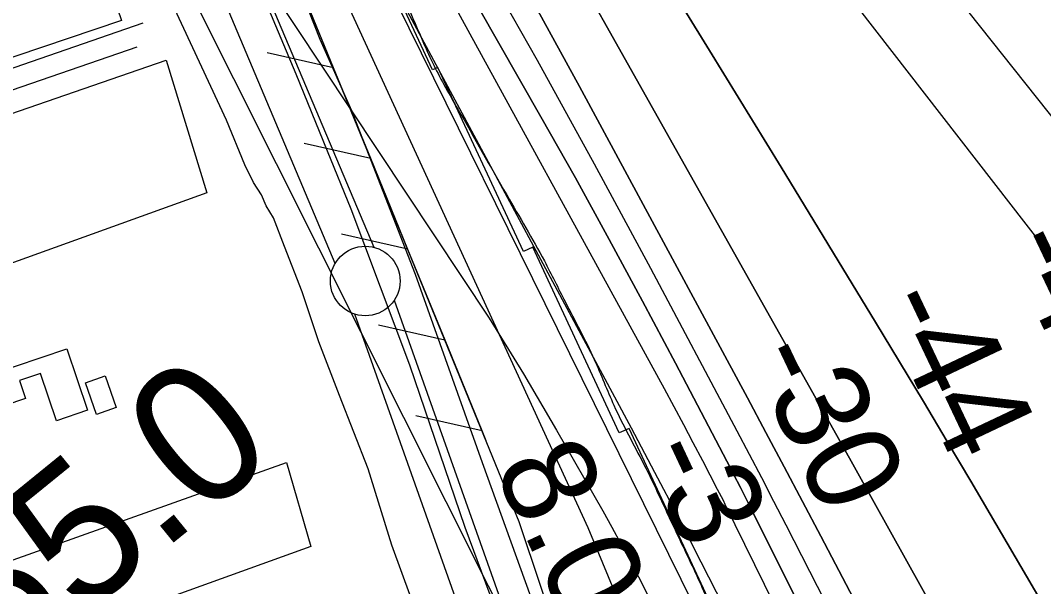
# Model space of a CAD drawing. Extents: x 3684037 to 3722149, y 433263 to 459021.
# Drawn here: x 3705202 to 3705935, y 447573 to 447979 of the extents above; entities that cross this region are included whole.
import ezdxf

# ---------------------------------------------------------------- set-up
doc = ezdxf.new("R2010")
doc.units = 0
for name, color, linetype in [('V-BLDG-OTLN', 7, 'Continuous'), ('V-DTCH-CNTR', 7, 'Continuous'), ('V-FLOD-BASE', 7, 'Continuous'), ('V-LEVE-TOET', 7, 'Continuous'), ('V-RIVR-EDGE', 7, 'Continuous'), ('V-RIVR-RANG', 7, 'Continuous'), ('V-RRAP-FSHR', 7, 'Continuous'), ('V-RRAP-RVMT', 7, 'Continuous'), ('V-SITE-VEGE', 7, 'Continuous'), ('V-SURV-IDEN', 7, 'Continuous'), ('V-SURV-LINE', 7, 'Continuous'), ('V-TOPO-DPTH', 7, 'Continuous'), ('V-TOPO-MAJR', 7, 'Continuous'), ('V-TOPO-MINR', 7, 'Continuous'), ('V-TOPO-SHOR', 7, 'Continuous'), ('V-TOPO-WATR', 7, 'Continuous'), ('V-UTIL-IDEN', 7, 'Continuous')]:
    doc.layers.add(name, color=color, linetype=linetype)

msp = doc.modelspace()

# ---------------------------------------------------------------- linework, layer by layer
at = {"layer": 'V-BLDG-OTLN'}
for points in [[(3705132.49, 447681.61), (3705115.88, 447730.81), (3705125.83, 447734.17), (3705124.98, 447736.71), (3705135.15, 447740.15), (3705135.63, 447738.72), (3705170.48, 447750.48), (3705179.21, 447724.63), (3705234.67, 447743.36), (3705249.59, 447699.15), (3705227.33, 447691.64), (3705215.88, 447725.56), (3705200.86, 447720.48), (3705205.18, 447707.68), (3705190.42, 447702.7), (3705192.04, 447697.91), (3705170.99, 447690.8), (3705169.84, 447694.22)], [(3705256.16, 447696.21), (3705248.18, 447718.82), (3705262.27, 447723.79), (3705270.24, 447701.18)]]:
    msp.add_lwpolyline(points, close=True, dxfattribs=at)
at = {"layer": 'V-DTCH-CNTR'}
msp.add_lwpolyline([(3705289.37, 447977.01), (3704951.54, 447860.04), (3704943.35, 447857.26), (3704679.55, 447767.66), (3704614.85, 447743.57), (3704504.65, 447702.53), (3704253.27, 447610.15)], dxfattribs=at)
at = {"layer": 'V-FLOD-BASE'}
msp.add_lwpolyline([(3706069.54, 446299.39), (3706032.11, 446386.4), (3705989.42, 446486.6), (3705944.62, 446589.43), (3705894.55, 446702.81), (3705831.3, 446847.3), (3705774.38, 446975.45), (3705730.63, 447077.22), (3705683.72, 447187.44), (3705619.95, 447341.95), (3705574.09, 447470.09), (3705520.34, 447615.11), (3705480.81, 447731.65), (3705438.65, 447843.45), (3705421.78, 447885.11), (3705399.12, 447940.48), (3705358.01, 448038.57), (3705317.95, 448129.79), (3705282.11, 448213.64)], dxfattribs=at)
at = {"layer": 'V-LEVE-TOET'}
for points in [[(3705156.29, 448436.48), (3705207.43, 448369.51), (3705261.2, 448300.94), (3705305.48, 448229.22), (3705318.66, 448202.33), (3705334.47, 448162.25), (3705356.08, 448110.57), (3705387.7, 448037.8), (3705416.17, 447965.55), (3705438.83, 447914.4), (3705454.11, 447874.85), (3705484.68, 447796.8), (3705532.64, 447661.8), (3705573.75, 447547.9)], [(3705494.65, 447528.93), (3705467.77, 447602.23), (3705450.91, 447657.07), (3705430.35, 447709.8), (3705415.6, 447748.3), (3705403.48, 447784.16), (3705390.83, 447816.86), (3705382.92, 447837.42), (3705377.65, 447845.86), (3705374.49, 447853.77), (3705368.69, 447862.74), (3705362.36, 447875.39), (3705349.19, 447907.56), (3705312.29, 447987.19), (3705275.4, 448079.48), (3705258, 448124.83), (3705241.14, 448167.54), (3705229.54, 448196.02), (3705220.06, 448220.28), (3705201.08, 448250.86)]]:
    msp.add_lwpolyline(points, dxfattribs=at)
at = {"layer": 'V-RIVR-EDGE'}
msp.add_spline([(3705459.26, 448025.43), (3705478.18, 447991.02), (3705490.65, 447962.68), (3705497.89, 447946.89), (3705515.2, 447915.31), (3705550.22, 447853.76), (3705577.2, 447806.38), (3705592.09, 447777.23), (3705613.01, 447735.52), (3705627.09, 447702.74), (3705648.41, 447660.63), (3705670.94, 447613.26), (3705688.64, 447575.61), (3705703.12, 447542.82), (3705728.05, 447487.77), (3705750.16, 447433.12), (3705764.23, 447399.52), (3705787.56, 447350.54), (3705800.43, 447321.8), (3705823.77, 447277.66), (3705853.13, 447212.89), (3705867.2, 447179.7), (3705884.51, 447148.52), (3705906.22, 447095.49), (3705936, 447039.61), (3705952.47, 446996.31), (3705954.47, 446986.6), (3705964.51, 446959.07), (3705978.19, 446928.31), (3706001.93, 446883.77), (3706017.22, 446850.17), (3706031.3, 446824.25), (3706060.3, 446774.85), (3706084.87, 446736.78), (3706095.75, 446723.41), (3706096.15, 446720.17), (3706091.28, 446714.52), (3706089.66, 446713.31), (3706090.46, 446708.86), (3706096.11, 446705.61), (3706102.98, 446703.57), (3706108.63, 446696.69), (3706116.28, 446683.32), (3706129.96, 446657.01), (3706163.36, 446591.82), (3706169.39, 446575.63), (3706187.09, 446537.58), (3706212.81, 446473.62), (3706230.09, 446432.33), (3706247.4, 446398.32), (3706265.12, 446371.19), (3706278.81, 446345.27), (3706293.68, 446309.65), (3706314.59, 446262.29), (3706333.51, 446225.85), (3706356.04, 446180.1), (3706380.19, 446133.54), (3706396.28, 446102.36), (3706412.79, 446074.82), (3706429.69, 446038.79), (3706446.98, 445997.91), (3706455.38, 445962.3), (3706478.24, 445886.22), (3706492.71, 445852.22), (3706510.4, 445809.72), (3706528.1, 445771.66), (3706558.26, 445705.27), (3706582.81, 445657.09), (3706597.69, 445624.3), (3706628.26, 445558.31), (3706659.61, 445483.02), (3706677.69, 445432.84), (3706696.97, 445381.03), (3706750.05, 445262.42), (3706782.63, 445193.19), (3706806.77, 445141.78), (3706827.68, 445093.6), (3706850.97, 445029.25), (3706864.2, 444984.33), (3706871.8, 444949.54), (3706889.46, 444896.93), (3706899.9, 444865.77), (3706912.35, 444832.17), (3706928.85, 444798.16), (3706942.54, 444773.46), (3706966.27, 444725.28), (3706990.42, 444679.53), (3707016.98, 444624.47), (3707033.86, 444586.01), (3707080.51, 444481.98), (3707095.38, 444444.74), (3707112.27, 444405.07), (3707123.13, 444381.18), (3707171.39, 444273.5), (3707203.15, 444200.64), (3707218.02, 444163.8), (3707250.2, 444096.19), (3707257.43, 444074.34), (3707269.88, 444041.55), (3707288.36, 443990.56), (3707304.03, 443950.08), (3707342.97, 443837.97), (3707365.86, 443772.01), (3707378.69, 443728.71), (3707379.87, 443714.15), (3707381.06, 443702.82), (3707387.47, 443682.18), (3707398.33, 443657.08), (3707418.05, 443619.03), (3707438.98, 443578.54), (3707454.25, 443542.11), (3707473.14, 443492.73), (3707483.18, 443464.39), (3707531.06, 443368.04), (3707542.73, 443344.96), (3707550.76, 443323.91), (3707556.78, 443302.46), (3707556.76, 443297.61), (3707558.76, 443289.12), (3707568.43, 443273.32), (3707583.72, 443244.57), (3707593.78, 443221.9), (3707598.21, 443213.4), (3707609.51, 443204.88), (3707611.91, 443195.17), (3707611.87, 443180.61), (3707615.48, 443168.07), (3707621.91, 443150.26), (3707634.38, 443126.78), (3707648.07, 443102.08), (3707655.3, 443081.84), (3707660.54, 443073.33), (3707674.23, 443051.47), (3707678.64, 443034.07), (3707682.63, 443015.46), (3707689.47, 442998.45), (3707701.92, 442964.46), (3707713.96, 442928.44), (3707721.18, 442903.35), (3707726.4, 442888.78), (3707738.08, 442871.77), (3707743.71, 442857.2), (3707744.49, 442845.06), (3707747.27, 442826.05), (3707753.71, 442815.52), (3707762.98, 442801.35), (3707770.21, 442783.94), (3707772.59, 442762.1), (3707776.17, 442738.23), (3707779.76, 442720.03), (3707786.59, 442702.62), (3707805.5, 442663.35), (3707822.8, 442627.32), (3707832.03, 442599.39), (3707839.25, 442573.9), (3707845.68, 442561.35), (3707852.54, 442552.44), (3707860.19, 442541.9), (3707869.47, 442530.56), (3707886.39, 442507.87), (3707898.86, 442479.94), (3707916.14, 442434.61), (3707928.58, 442395.76), (3707943.44, 442356.5), (3707965.58, 442316.41), (3707989.73, 442269.04), (3708009.84, 442227.74), (3708024.72, 442192.53), (3708061.32, 442114.39), (3708074.2, 442088.48), (3708094.31, 442045.57), (3708116.02, 441996.58), (3708126.06, 441968.25), (3708137.69, 441927.79), (3708147.33, 441899.46), (3708157.76, 441868.3), (3708179.06, 441812.44), (3708203.96, 441746.87), (3708227.69, 441693.84), (3708249.81, 441646.07), (3708265.1, 441615.3), (3708271.52, 441595.87), (3708278.37, 441582.11), (3708308.11, 441508.44), (3708330.63, 441457.84), (3708349.91, 441405.22), (3708369.56, 441340.07), (3708384.01, 441295.55), (3708395.26, 441268.43), (3708411.76, 441234.83), (3708423.42, 441209.33), (3708441.12, 441169.65), (3708458.42, 441135.24), (3708469.27, 441110.55), (3708475.29, 441089.1), (3708486.95, 441061.57), (3708507.06, 441017.45), (3708523.54, 440978.59), (3708539.2, 440935.69), (3708564.14, 440883.06), (3708587.09, 440841.35), (3708595.14, 440826.77), (3708600.35, 440809.37), (3708606.75, 440778.22), (3708615.59, 440755.15), (3708636.86, 440692.01), (3708652.92, 440644.26), (3708673.41, 440592.04), (3708688.69, 440554.4), (3708705.96, 440506.64), (3708725.66, 440462.92), (3708743.35, 440422.44), (3708759.44, 440387.62), (3708800.05, 440293.31), (3708820.96, 440246.35), (3708835.03, 440211.54), (3708849.1, 440180.36), (3708876.06, 440124.9), (3708892.16, 440093.72), (3708912.28, 440054.85), (3708922.33, 440030.97), (3708931.96, 439999.81), (3708939.18, 439978.77), (3708948.02, 439954.08), (3708952.41, 439931.83), (3708956, 439911.6), (3708960.02, 439899.46), (3708969.65, 439870.32), (3708986.94, 439829.84), (3708999.38, 439794.22), (3709014.65, 439755.37), (3709034.75, 439705.18), (3709046.8, 439671.58), (3709063.28, 439633.13), (3709075.77, 439614.5), (3709093.1, 439592.62), (3709106, 439574.39), (3709121.71, 439548.87), (3709151.47, 439484.1), (3709171.6, 439447.25), (3709197.38, 439407.56), (3709211.05, 439376.8), (3709222.31, 439350.08), (3709240.4, 439308.79), (3709252.87, 439281.67), (3709266.15, 439254.94), (3709270.98, 439245.63), (3709296.34, 439199.88), (3709313.22, 439158.99), (3709331.31, 439114.87), (3709341.34, 439082.5), (3709360.25, 439046.46), (3709378.76, 439008.81), (3709407.72, 438944.44), (3709416.41, 438923.63)], degree=3, dxfattribs=at)
at = {"layer": 'V-RRAP-FSHR'}
for p, q in [((3705426.05, 447945.09), (3705378.43, 447955.88)), ((3705426.05, 447945.09), (3705378.43, 447955.88)), ((3705452.69, 447879.91), (3705405.06, 447890.71)), ((3705452.69, 447879.91), (3705405.06, 447890.71)), ((3705479.32, 447814.74), (3705431.7, 447825.53)), ((3705479.32, 447814.74), (3705431.7, 447825.53)), ((3705505.95, 447749.56), (3705458.33, 447760.36)), ((3705505.95, 447749.56), (3705458.33, 447760.36)), ((3705532.58, 447684.39), (3705484.96, 447695.18)), ((3705532.58, 447684.39), (3705484.96, 447695.18))]:
    msp.add_line(p, q, dxfattribs=at)
for points in [[(3706624.05, 445324.52), (3706335.74, 445974.6), (3706211.12, 446060.34), (3705941.18, 446680.14), (3705638.1, 447383.27), (3705559.25, 447619.14), (3705292.92, 448270.89), (3705041.4, 448568.62), (3705014.25, 448591.97), (3704849.52, 448620.32), (3704832.09, 448641.18), (3704566.71, 448979.59), (3704022.21, 449672.18), (3703637.9, 450137.19), (3703233.42, 450593.66)], [(3705110.68, 448422.87), (3705932.45, 446784.27), (3706683.04, 445264.96), (3707275.15, 443771.41)], [(3705426.08, 447945.01), (3705399.45, 448010.19)], [(3705452.72, 447879.84), (3705426.08, 447945.01)], [(3705479.35, 447814.66), (3705452.72, 447879.84)], [(3705505.98, 447749.49), (3705479.35, 447814.66)], [(3705532.62, 447684.31), (3705505.98, 447749.49)], [(3705535.49, 447677.28), (3705532.61, 447684.31)]]:
    msp.add_lwpolyline(points, dxfattribs=at)
at = {"layer": 'V-RRAP-RVMT'}
msp.add_lwpolyline([(3705694.36, 447564.54), (3705637.93, 447686.21), (3705630.76, 447682.88), (3705568.94, 447816.17), (3705562.15, 447813.07), (3705500.85, 447945.3), (3705497, 447943.47), (3705436.31, 448074.29), (3705435.66, 448073.99), (3705373.5, 448207.71), (3705360.21, 448201.57), (3705307.13, 448316.13), (3705285.76, 448304.71), (3705219.5, 448427.38), (3705208.9, 448421.32), (3705138.31, 448545.76), (3705115.83, 448532.94), (3705049.39, 448650.15), (3705004.42, 448624.71), (3704928.69, 448758.07), (3704914.75, 448750.08), (3704884.16, 448803.45), (3705314.54, 449029.89)], dxfattribs=at)
at = {"layer": 'V-SITE-VEGE'}
for points in [[(3705922.3, 446849.55), (3705769.67, 447226.24), (3705608.56, 447614.81), (3705401.66, 448066.16), (3705333.82, 448218.87), (3705333.82, 448223.96), (3705335.52, 448225.66), (3705340.61, 448229.05), (3705350.78, 448229.04), (3705355.88, 448225.65), (3705710.34, 447506.2), (3705961.34, 446941.17), (3705981.69, 446895.35), (3705983.38, 446883.48), (3705981.69, 446880.09), (3705959.62, 446858.03), (3705944.35, 446844.46), (3705927.38, 446839.38)], [(3705274.07, 447979.01), (3704951.54, 447870.01), (3704923.63, 447959.13), (3705171.01, 448045.53), (3705243.5, 448068.12)], [(3704970.82, 447834.77), (3705305.98, 447950.41), (3705335.22, 447855.31), (3704990.75, 447731.03)], [(3705129.7, 447568.09), (3705392.38, 447661.8), (3705409.65, 447601.28), (3705178.89, 447518.21), (3705170.92, 447538.82), (3705137.67, 447528.18)]]:
    msp.add_lwpolyline(points, close=True, dxfattribs=at)
at = {"layer": 'V-SURV-LINE'}
for points in [[(3705295.56, 448194.21), (3705454.83, 447816.2)], [(3705427.18, 447804.57), (3705267.91, 448182.57)], [(3705469.58, 447778.15), (3705620.41, 447352.84)], [(3705592.13, 447342.82), (3705441.31, 447768.13)]]:
    msp.add_lwpolyline(points, dxfattribs=at)
msp.add_circle((3705448.77, 447791.97), 25, dxfattribs=at)
at = {"layer": 'V-TOPO-DPTH'}
for points in [[(3706098.38, 447121.23), (3705789.04, 447677.24), (3705447.44, 448285.39), (3705438.29, 448301.54), (3705429.06, 448317.64), (3705419.71, 448333.68), (3705410.29, 448349.66), (3705400.68, 448365.54), (3705390.91, 448381.31), (3705380.9, 448396.93), (3705370.72, 448412.45), (3705344.87, 448451.2), (3705321.5, 448485.92), (3705297.92, 448520.49), (3705274.04, 448554.85), (3705249.95, 448589.07), (3704934.32, 449033.23), (3704926.32, 449044.46), (3704918.28, 449055.68), (3704910.21, 449066.86), (3704902.12, 449078.03), (3704655.5, 449417.12)], [(3704655.5, 449417.12), (3704902.12, 449078.03), (3704910.21, 449066.86), (3704918.28, 449055.68), (3704926.32, 449044.46), (3704934.32, 449033.23), (3705249.95, 448589.07), (3705274.04, 448554.85), (3705297.92, 448520.49), (3705321.5, 448485.92), (3705344.87, 448451.2), (3705370.72, 448412.45), (3705380.9, 448396.93), (3705390.91, 448381.31), (3705400.68, 448365.54), (3705410.29, 448349.66), (3705419.71, 448333.68), (3705429.06, 448317.64), (3705438.29, 448301.54), (3705447.44, 448285.39), (3705789.04, 447677.24), (3706098.38, 447121.23)], [(3705202.63, 448538.55), (3705320.25, 448355.57), (3705324, 448349.63), (3705327.69, 448343.64), (3705331.28, 448337.6), (3705334.8, 448331.52), (3705574.77, 447909.83), (3705599.44, 447865.93), (3705623.8, 447821.86), (3705647.68, 447777.54), (3705671.25, 447733.04), (3705708, 447662.76), (3705712.94, 447653.26), (3705717.83, 447643.74), (3705722.67, 447634.19), (3705727.48, 447624.62), (3706113.16, 446851.05)], [(3706113.16, 446851.05), (3705727.48, 447624.62), (3705722.67, 447634.19), (3705717.83, 447643.74), (3705712.94, 447653.26), (3705708, 447662.76), (3705671.25, 447733.04), (3705647.68, 447777.54), (3705623.8, 447821.86), (3705599.44, 447865.93), (3705574.77, 447909.83), (3705334.8, 448331.52), (3705331.28, 448337.6), (3705327.69, 448343.64), (3705324, 448349.63), (3705320.25, 448355.57), (3705202.63, 448538.55)], [(3705848.39, 447469.47), (3705775.49, 447608.79), (3705762.41, 447633.67), (3705749.28, 447658.53), (3705736.05, 447683.33), (3705722.77, 447708.11), (3705602.46, 447931.54), (3705562.95, 448003.92), (3705522.88, 448075.99), (3705481.98, 448147.59), (3705440.53, 448218.88), (3705381.05, 448319.84), (3705368.78, 448340.33), (3705356.32, 448360.7), (3705343.57, 448380.88), (3705330.63, 448400.95)], [(3705330.63, 448400.95), (3705343.57, 448380.88), (3705356.32, 448360.7), (3705368.78, 448340.33), (3705381.05, 448319.84), (3705440.53, 448218.88), (3705481.98, 448147.59), (3705522.88, 448075.99), (3705562.95, 448003.92), (3705602.46, 447931.54), (3705722.77, 447708.11), (3705736.05, 447683.33), (3705749.28, 447658.53), (3705762.41, 447633.67), (3705775.49, 447608.79), (3705848.39, 447469.47)], [(3705247.94, 448390.77), (3705254.63, 448379.96), (3705261.21, 448369.09), (3705316.01, 448277.08), (3705349.52, 448219.94), (3705382.52, 448162.5), (3705414.74, 448104.62), (3705446.44, 448046.45), (3705639.35, 447686.68), (3705656.3, 447654.72), (3705673.07, 447622.65), (3705689.54, 447590.44), (3705705.81, 447558.13)], [(3705932.88, 447563.26), (3705905.05, 447610.72), (3705882.98, 447648.23), (3705866.04, 447676.86), (3705849.03, 447705.44), (3705831.89, 447733.95), (3705814.66, 447762.41), (3705747.01, 447873.64), (3705695.7, 447957.56), (3705644.14, 448041.32), (3705592.2, 448124.85), (3705540, 448208.21), (3705431.54, 448380.56), (3705425.75, 448389.6)], [(3705425.75, 448389.6), (3705431.54, 448380.56), (3705540, 448208.21), (3705592.2, 448124.85), (3705644.14, 448041.32), (3705695.7, 447957.56), (3705747.01, 447873.64), (3705814.66, 447762.41), (3705831.89, 447733.95), (3705849.03, 447705.44), (3705866.04, 447676.86), (3705882.98, 447648.23), (3705905.05, 447610.72), (3705932.88, 447563.26)]]:
    msp.add_lwpolyline(points, dxfattribs=at)
at = {"layer": 'V-TOPO-MAJR'}
msp.add_lwpolyline([(3704567.62, 449618.47), (3704793.52, 449307.85), (3704820.93, 449270.11), (3704848.31, 449232.33), (3704875.63, 449194.52), (3704902.92, 449156.69), (3704942.34, 449101.96), (3704949.92, 449091.49), (3704957.53, 449081.04), (3704965.2, 449070.63), (3704972.9, 449060.24), (3705033.47, 448978.92), (3705071.72, 448928.07), (3705110.3, 448877.48), (3705149.36, 448827.25), (3705188.74, 448777.28), (3705437.94, 448464.19), (3705452.6, 448445.49), (3705467.07, 448426.63), (3705481.24, 448407.56), (3705495.22, 448388.35), (3705508.87, 448368.89), (3705522.27, 448349.28), (3705947.23, 447800.68)], dxfattribs=at)
at = {"layer": 'V-TOPO-MINR'}
for points in [[(3704655.5, 449417.12), (3704902.12, 449078.03), (3704910.21, 449066.86), (3704918.28, 449055.68), (3704926.32, 449044.46), (3704934.32, 449033.23), (3705249.95, 448589.07), (3705274.04, 448554.85), (3705297.92, 448520.49), (3705321.5, 448485.92), (3705344.87, 448451.2), (3705370.72, 448412.45), (3705380.9, 448396.93), (3705390.91, 448381.31), (3705400.68, 448365.54), (3705410.29, 448349.66), (3705419.71, 448333.68), (3705429.06, 448317.64), (3705438.29, 448301.54), (3705447.44, 448285.39), (3705789.04, 447677.24), (3706098.38, 447121.23)], [(3704445.88, 449360.55), (3704468.81, 449329.57), (3704734.68, 448974.1), (3704743.84, 448961.5), (3704752.75, 448948.74), (3704761.31, 448935.73), (3705537.74, 447765.28), (3705562.25, 447725.38), (3705586.02, 447685.01), (3705619.1, 447626.95), (3705625.68, 447615.21), (3705632.15, 447603.4), (3705638.44, 447591.5), (3705644.61, 447579.54), (3705942.72, 446991.71)], [(3704954.86, 448943.64), (3705324.69, 448374.9), (3705332.34, 448362.94), (3705339.88, 448350.91), (3705347.25, 448338.77), (3705354.5, 448326.56), (3705487.91, 448098.21), (3705530.34, 448024.54), (3705572.16, 447950.52), (3705613.05, 447875.99), (3705653.33, 447801.12), (3705715.16, 447684.48), (3705724.03, 447667.65), (3705732.84, 447650.8), (3705741.58, 447633.9), (3705750.26, 447616.98), (3705947.77, 447229.89)], [(3705202.63, 448538.55), (3705320.25, 448355.57), (3705324, 448349.63), (3705327.69, 448343.64), (3705331.28, 448337.6), (3705334.8, 448331.52), (3705574.77, 447909.83), (3705599.44, 447865.93), (3705623.8, 447821.86), (3705647.68, 447777.54), (3705671.25, 447733.04), (3705708, 447662.76), (3705712.94, 447653.26), (3705717.83, 447643.74), (3705722.67, 447634.19), (3705727.48, 447624.62), (3706113.16, 446851.05)], [(3705527.53, 448430.62), (3706012.6, 447819.93)], [(3705273.43, 448413.53), (3705317.75, 448344.99), (3705319.41, 448342.35), (3705321.04, 448339.68), (3705322.61, 448336.98), (3705324.14, 448334.26), (3705663.05, 447714.78), (3705670.02, 447701.94), (3705676.94, 447689.06), (3705683.77, 447676.14), (3705690.55, 447663.19), (3705701.23, 447642.6), (3705702.61, 447639.92), (3705703.98, 447637.23), (3705705.34, 447634.53), (3705706.68, 447631.82), (3705784.44, 447473.49)], [(3705330.63, 448400.95), (3705343.57, 448380.88), (3705356.32, 448360.7), (3705368.78, 448340.33), (3705381.05, 448319.84), (3705440.53, 448218.88), (3705481.98, 448147.59), (3705522.88, 448075.99), (3705562.95, 448003.92), (3705602.46, 447931.54), (3705722.77, 447708.11), (3705736.05, 447683.33), (3705749.28, 447658.53), (3705762.41, 447633.67), (3705775.49, 447608.79), (3705848.39, 447469.47)], [(3705425.75, 448389.6), (3705431.54, 448380.56), (3705540, 448208.21), (3705592.2, 448124.85), (3705644.14, 448041.32), (3705695.7, 447957.56), (3705747.01, 447873.64), (3705814.66, 447762.41), (3705831.89, 447733.95), (3705849.03, 447705.44), (3705866.04, 447676.86), (3705882.98, 447648.23), (3705905.05, 447610.72), (3705932.88, 447563.26)]]:
    msp.add_lwpolyline(points, dxfattribs=at)
at = {"layer": 'V-TOPO-SHOR'}
msp.add_lwpolyline([(3705285.02, 447959.86), (3705063.58, 447883.43), (3704949.92, 447845)], dxfattribs=at)
at = {"layer": 'V-TOPO-WATR'}
msp.add_lwpolyline([(3705247.94, 448390.77), (3705254.63, 448379.96), (3705261.21, 448369.09), (3705316.01, 448277.08), (3705349.52, 448219.94), (3705382.52, 448162.5), (3705414.74, 448104.62), (3705446.44, 448046.45), (3705639.35, 447686.68), (3705656.3, 447654.72), (3705673.07, 447622.65), (3705689.54, 447590.44), (3705705.81, 447558.13)], dxfattribs=at)
at = {"layer": 'V-UTIL-IDEN'}
for points in [[(3706624.05, 445324.52), (3706335.74, 445974.6), (3706211.12, 446060.34), (3705941.18, 446680.14), (3705638.1, 447383.27), (3705559.25, 447619.14), (3705292.92, 448270.89), (3705041.4, 448568.62), (3705014.25, 448591.97), (3704849.52, 448620.32), (3704832.09, 448641.18), (3704566.71, 448979.59), (3704022.21, 449672.18), (3703637.9, 450137.19), (3703233.42, 450593.66)], [(3705426.08, 447945.01), (3705399.45, 448010.19)], [(3705452.72, 447879.84), (3705426.08, 447945.01)], [(3705479.35, 447814.66), (3705452.72, 447879.84)], [(3705505.98, 447749.49), (3705479.35, 447814.66)], [(3705532.62, 447684.31), (3705505.98, 447749.49)], [(3705535.49, 447677.28), (3705532.61, 447684.31)]]:
    msp.add_lwpolyline(points, dxfattribs=at)

# ---------------------------------------------------------------- texts
at = {"layer": 'V-RIVR-RANG'}
for s, rotation, p in [('-49', 295.33969, (3705906.31, 447818.62)), ('-44', 295.33969, (3705815.83, 447776.04)), ('-30', 295.33969, (3705723.31, 447737.76)), ('8.0', 295.05833, (3705540.3, 447657.95)), ('-3', 295.05833, (3705645.97, 447668.03))]:
    msp.add_text(s, height=67, rotation=rotation, dxfattribs=at).set_placement(p)
at = {"layer": 'V-SURV-IDEN'}
msp.add_text('854+65.0', height=100, rotation=39.11299, dxfattribs=at).set_placement((3704952.78, 447312.67))

doc.saveas('drawing.dxf')
